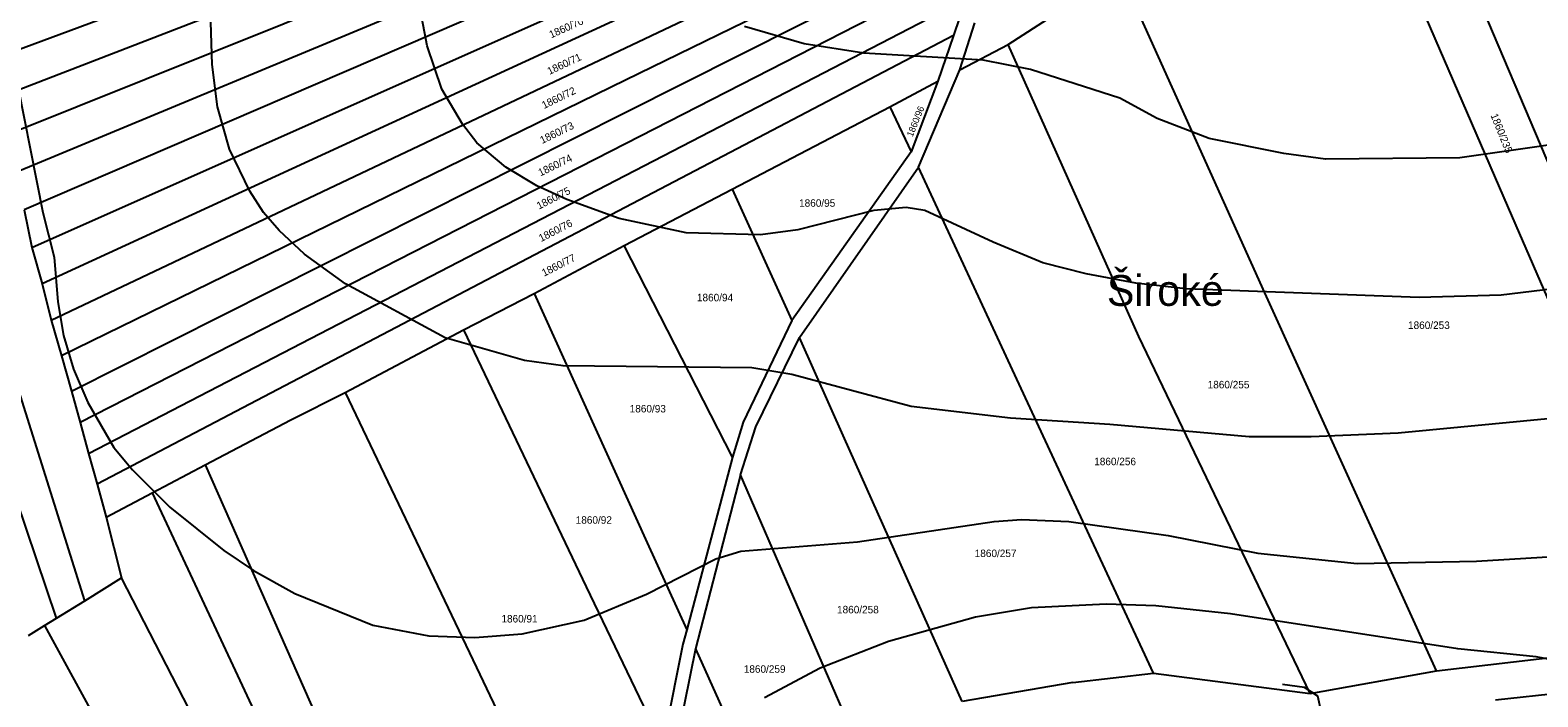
# Model space of a CAD drawing. Extents: x -555860 to -552701, y -1187050 to -1182291.
# Drawn here: x -554246.1 to -553903.7, y -1183412.8 to -1183261.4 of the extents above; entities that cross this region are included whole.
import ezdxf

# ---------------------------------------------------------------- set-up
doc = ezdxf.new("R2010")
doc.units = 0
for name, color, linetype in [('LEG_2b', 7, 'Continuous'), ('Level 40', 7, 'Continuous'), ('Level 41', 7, 'Continuous'), ('navrh_BV', 7, 'Continuous'), ('Parcelní čísla', 7, 'Continuous')]:
    doc.layers.add(name, color=color, linetype=linetype)

msp = doc.modelspace()

# ---------------------------------------------------------------- linework, layer by layer
at = {"layer": 'Level 40'}
msp.add_lwpolyline([(-553899.84, -1183349.5), (-553935.4, -1183352.89), (-553955.16, -1183353.74), (-553969.27, -1183353.74), (-554000.88, -1183350.91), (-554023.46, -1183349.5), (-554046.04, -1183346.82), (-554073.13, -1183339.62), (-554082.16, -1183338.07), (-554125.06, -1183337.65), (-554133.81, -1183336.38), (-554151.87, -1183331.3), (-554174.45, -1183319.02), (-554183.77, -1183312.25), (-554189.55, -1183306.89), (-554193.08, -1183302.79), (-554196.18, -1183298), (-554200.84, -1183288.4), (-554203.52, -1183278.8), (-554204.79, -1183269.21), (-554205.07, -1183259.61)], dxfattribs=at)
at = {"layer": 'Level 41'}
for points in [[(-553900.12, -1183320.15), (-553911.98, -1183321.56), (-553930.6, -1183322.13), (-553983.66, -1183320.15), (-553994.95, -1183318.88), (-554006.24, -1183316.76), (-554016.12, -1183314.22), (-554027.41, -1183309.57), (-554042.93, -1183302.37), (-554047.17, -1183301.66), (-554054.5, -1183302.37), (-554071.72, -1183306.74), (-554080.19, -1183307.87), (-554097.12, -1183307.45), (-554112.36, -1183304.21), (-554124.21, -1183299.83), (-554130.99, -1183296.73), (-554138.04, -1183292.49), (-554144.68, -1183286.99), (-554147.92, -1183282.76), (-554152.58, -1183274.85), (-554155.96, -1183264.97), (-554157.8, -1183255.1)], [(-553884.88, -1183285.15), (-553921.43, -1183290.41), (-553951.91, -1183290.7), (-553961.37, -1183289.39), (-553978.3, -1183286), (-553990.15, -1183281.48), (-553998.62, -1183276.83), (-554018.94, -1183270.34), (-554029.67, -1183268.22), (-554056.76, -1183266.67), (-554070.31, -1183264.55), (-554083.85, -1183260.6)], [(-554250.23, -1183267.23), (-554243.18, -1183302.79), (-554240.64, -1183312.95), (-554239.79, -1183323.11), (-554238.52, -1183330.73), (-554236.26, -1183338.35), (-554233.01, -1183345.98), (-554227.09, -1183356.14), (-554222.85, -1183361.22), (-554214.39, -1183369.68), (-554202.11, -1183379.56), (-554195.34, -1183384.08), (-554186.02, -1183389.3), (-554168.24, -1183396.49), (-554155.54, -1183398.89), (-554145.1, -1183399.32), (-554134.38, -1183398.47), (-554120.26, -1183395.36), (-554106.15, -1183389.44), (-554090.35, -1183381.4), (-554084.7, -1183379.7), (-554058.17, -1183377.58), (-554027.13, -1183372.93), (-554020.92, -1183372.5), (-554010.19, -1183372.93), (-553987.61, -1183376.17), (-553967.29, -1183380.12), (-553944.71, -1183382.52), (-553917.62, -1183381.96), (-553875.29, -1183379.42)], [(-553864.84, -1183411.17), (-553904.07, -1183403.69), (-553921.85, -1183401.86), (-553973.5, -1183393.95), (-553990.44, -1183392.12), (-554001.72, -1183391.7), (-554018.66, -1183392.54), (-554031.36, -1183394.66), (-554051.12, -1183400.16), (-554066.64, -1183406.23), (-554079.34, -1183413)], [(-553903.23, -1183429.23), (-553913.1, -1183430.5), (-553935.68, -1183435.58), (-553941.33, -1183436.29), (-553948.38, -1183434.88), (-553950.92, -1183433.75), (-553954.59, -1183431.07), (-553955.18, -1183429.66), (-553955.16, -1183427.68), (-553952.81, -1183416.35), (-553953.66, -1183412.64), (-553956.7, -1183410.63), (-553961.65, -1183409.97)]]:
    msp.add_lwpolyline(points, dxfattribs=at)
at = {"layer": 'navrh_BV'}
for p, q in [((-553937.68, -1183206.08), (-553879.44, -1183343.28)), ((-554110.9, -1183214.67), (-554254.72, -1183268.12)), ((-553947.54, -1183215.88), (-553910.4, -1183301.79)), ((-554252.87, -1183276.57), (-554110.97, -1183221.67)), ((-554110.88, -1183265.45), (-554022.09, -1183223.21)), ((-554110.94, -1183228.92), (-554251.11, -1183285.09)), ((-554025.31, -1183231), (-554110.9, -1183272.79)), ((-554249.35, -1183293.64), (-554110.88, -1183236.1)), ((-554110.99, -1183280.1), (-554028.13, -1183238.45)), ((-554110.91, -1183243.47), (-554247.49, -1183302.2)), ((-554030.79, -1183246.23), (-554110.92, -1183287.26)), ((-554023.97, -1183264.65), (-553998.5, -1183248.19)), ((-553965.65, -1183321.06), (-553998.5, -1183248.19)), ((-554245.7, -1183310.79), (-554111, -1183250.87)), ((-554110.98, -1183294.42), (-554033.58, -1183254.3)), ((-554033.58, -1183254.3), (-554036.39, -1183262.62)), ((-554110.89, -1183258.11), (-554243.38, -1183319.03)), ((-554036.39, -1183262.62), (-554110.94, -1183301.7)), ((-554036.39, -1183262.62), (-554039.92, -1183272.97)), ((-554034.95, -1183270.4), (-554031.56, -1183259.78)), ((-554241.33, -1183327.24), (-554110.88, -1183265.45)), ((-554034.95, -1183270.4), (-554023.97, -1183264.65)), ((-553994.31, -1183330.94), (-554023.97, -1183264.65)), ((-554110.9, -1183272.79), (-554238.99, -1183335.35)), ((-554050.84, -1183278.8), (-554039.92, -1183272.97)), ((-554039.92, -1183272.97), (-554046, -1183289.06)), ((-554044.35, -1183292.52), (-554034.95, -1183270.4)), ((-554086.64, -1183297.55), (-554050.84, -1183278.8)), ((-554050.84, -1183278.8), (-554046, -1183289.06)), ((-554236.71, -1183343.35), (-554110.99, -1183280.1)), ((-554110.92, -1183287.26), (-554234.74, -1183350.51)), ((-554046, -1183289.06), (-554073.09, -1183327.32)), ((-554071.34, -1183331.18), (-554044.35, -1183292.52)), ((-554022.04, -1183340.63), (-554044.35, -1183292.52)), ((-554232.82, -1183357.54), (-554110.98, -1183294.42)), ((-554111.15, -1183310.33), (-554086.64, -1183297.55)), ((-554086.64, -1183297.55), (-554073.09, -1183327.32)), ((-554247.49, -1183302.2), (-554245.7, -1183310.79)), ((-554110.94, -1183301.7), (-554230.87, -1183364.51)), ((-553910.4, -1183301.79), (-553890.91, -1183346.8)), ((-554245.7, -1183310.79), (-554243.38, -1183319.03)), ((-554131.62, -1183321.2), (-554111.15, -1183310.33)), ((-554086.59, -1183358.36), (-554111.15, -1183310.33)), ((-554243.38, -1183319.03), (-554241.33, -1183327.24)), ((-553926.73, -1183406.83), (-553965.65, -1183321.06)), ((-554147.69, -1183329.43), (-554131.62, -1183321.2)), ((-554131.62, -1183321.2), (-554105.96, -1183377.81)), ((-554241.33, -1183327.24), (-554238.99, -1183335.35)), ((-554073.09, -1183327.32), (-554084.14, -1183350.42)), ((-554233.66, -1183390.93), (-554252.75, -1183330.18)), ((-554174.58, -1183343.64), (-554147.69, -1183329.43)), ((-554147.69, -1183329.43), (-554119.83, -1183387.76)), ((-554081.32, -1183351.46), (-554071.34, -1183331.18)), ((-554061.16, -1183354.11), (-554071.34, -1183331.18)), ((-553955.37, -1183411.99), (-553994.31, -1183330.94)), ((-554240.12, -1183394.88), (-554261.01, -1183333.49)), ((-554238.99, -1183335.35), (-554236.71, -1183343.35)), ((-553990.96, -1183407.36), (-554022.04, -1183340.63)), ((-554236.71, -1183343.35), (-554234.74, -1183350.51)), ((-554186.88, -1183349.86), (-554174.58, -1183343.64)), ((-554174.58, -1183343.64), (-554144.71, -1183406.09)), ((-554234.74, -1183350.51), (-554232.82, -1183357.54)), ((-554206.37, -1183360.11), (-554186.88, -1183349.86)), ((-554084.14, -1183350.42), (-554086.59, -1183358.36)), ((-554084.77, -1183362.35), (-554081.32, -1183351.46)), ((-554034.39, -1183413.78), (-554061.16, -1183354.11)), ((-554232.82, -1183357.54), (-554230.87, -1183364.51)), ((-554086.59, -1183358.36), (-554096.97, -1183397.55)), ((-554218.41, -1183366.45), (-554206.37, -1183360.11)), ((-554206.37, -1183360.11), (-554175.98, -1183428.8)), ((-554230.87, -1183364.51), (-554228.86, -1183372)), ((-554084.77, -1183362.35), (-554095.01, -1183401.84)), ((-554060.68, -1183417.74), (-554084.77, -1183362.35)), ((-554228.86, -1183372), (-554218.41, -1183366.45)), ((-554218.41, -1183366.45), (-554185.89, -1183435.96)), ((-554228.86, -1183372), (-554225.38, -1183385.78)), ((-554105.96, -1183377.81), (-554096.97, -1183397.55)), ((-554233.66, -1183390.93), (-554225.38, -1183385.78)), ((-554195.66, -1183443.29), (-554225.38, -1183385.78)), ((-554119.83, -1183387.76), (-554102.47, -1183423.86)), ((-554240.12, -1183394.88), (-554233.66, -1183390.93)), ((-554242.84, -1183396.54), (-554240.12, -1183394.88)), ((-554246.49, -1183398.86), (-554242.84, -1183396.54)), ((-554242.84, -1183396.54), (-554211.23, -1183454.53)), ((-554096.97, -1183397.55), (-554097.83, -1183400.8)), ((-554097.83, -1183400.8), (-554102.47, -1183423.86)), ((-554095.01, -1183401.84), (-554100.07, -1183426.95)), ((-554095.01, -1183401.84), (-554080.71, -1183433.51)), ((-554144.71, -1183406.09), (-554115.67, -1183466.95)), ((-553926.73, -1183406.83), (-553897.55, -1183403.42)), ((-554009.3, -1183409.51), (-554034.39, -1183413.78)), ((-554009.3, -1183409.51), (-553990.96, -1183407.36)), ((-553990.96, -1183407.36), (-553955.37, -1183411.99)), ((-553955.37, -1183411.99), (-553926.73, -1183406.83)), ((-553897.94, -1183411.82), (-553913.31, -1183413.52))]:
    msp.add_line(p, q, dxfattribs=at)

# ---------------------------------------------------------------- texts
at = {"layer": 'LEG_2b'}
for s, height, rotation, p in [('1860/70', 1.7, 24, (-554127.77, -1183263.3)), ('1860/71', 1.7, 25, (-554128.17, -1183271.6)), ('1860/72', 1.7, 26, (-554129.39, -1183279.34)), ('1860/96', 1.5, 68, (-554045.69, -1183285.78)), ('1860/73', 1.7, 26, (-554129.8, -1183287.27)), ('1860/235', 1.7, 292, (-553914.46, -1183280.74)), ('1860/74', 1.7, 26, (-554130.2, -1183294.64)), ('1860/75', 1.7, 27, (-554130.53, -1183302.17)), ('1860/76', 1.7, 27, (-554130.06, -1183309.53)), ('1860/77', 1.7, 27, (-554129.37, -1183317.4))]:
    msp.add_text(s, height=height, rotation=rotation, dxfattribs=at).set_placement(p)
for s, p in [('1860/95', (-554071.46, -1183301.51)), ('1860/94', (-554094.66, -1183322.97)), ('1860/253', (-553933.16, -1183329.25)), ('1860/255', (-553978.67, -1183342.73)), ('1860/93', (-554109.93, -1183348.2)), ('1860/256', (-554004.43, -1183360.18)), ('1860/92', (-554122.19, -1183373.46)), ('1860/257', (-554031.57, -1183381.03)), ('1860/258', (-554062.84, -1183393.8)), ('1860/91', (-554139.06, -1183395.88)), ('1860/259', (-554084.02, -1183407.29))]:
    msp.add_text(s, height=1.7, dxfattribs=at).set_placement(p)
at = {"layer": 'Parcelní čísla'}
msp.add_text('Široké', height=7, dxfattribs=at).set_placement((-554001.55, -1183324.01))

doc.saveas('drawing.dxf')
